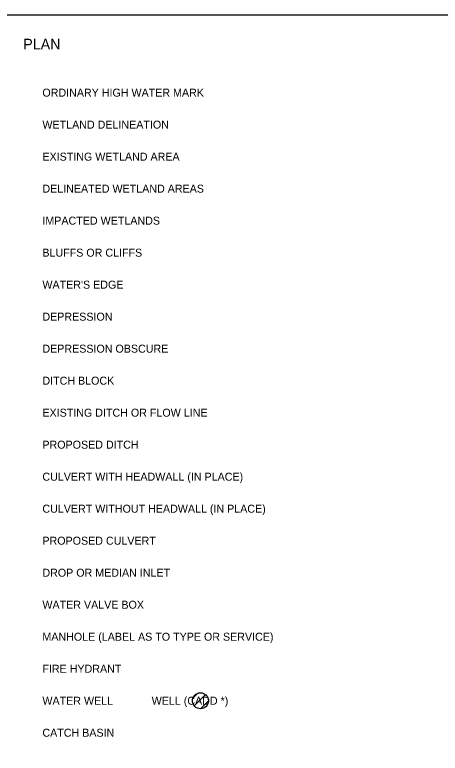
# Model space of a CAD drawing. Extents: x 49991.4 to 50021, y 49987.6 to 50011.4.
# Drawn here: x 50009.45 to 50012.64, y 49993.46 to 49999 of the extents above; entities that cross this region are included whole.
import ezdxf

# ---------------------------------------------------------------- set-up
doc = ezdxf.new("R2010")
doc.units = 0
doc.layers.add('Level 1', color=7, linetype='Continuous')
doc.layers.add('Level 2', color=7, linetype='Continuous')

msp = doc.modelspace()

# ---------------------------------------------------------------- linework, layer by layer
at = {"layer": 'Level 1'}
for p, q in [((50010.7828, 49993.874), (50010.8211, 49993.9122)), ((50010.7936, 49993.8169), (50010.8782, 49993.9014)), ((50010.8398, 49993.7952), (50010.8998, 49993.8552))]:
    msp.add_line(p, q, dxfattribs=at)
msp.add_lwpolyline([(49999.3835, 49998.9992), (50016.7501, 49998.9992), (50016.7501, 49987.7988), (49999.3835, 49987.7988)], close=True, dxfattribs=at)
msp.add_circle((50010.8398, 49993.8552), 0.06, dxfattribs=at)

# ---------------------------------------------------------------- texts
at = {"layer": 'Level 2'}
for s, height, p in [('PLAN', 0.08, (50009.5097, 49998.7392)), ('ORDINARY HIGH WATER MARK', 0.06, (50009.6535, 49998.3852)), ('WETLAND DELINEATION ', 0.06, (50009.6535, 49998.1452)), ('EXISTING WETLAND AREA', 0.06, (50009.6535, 49997.9052)), ('DELINEATED WETLAND AREAS ', 0.06, (50009.6535, 49997.6652)), ('IMPACTED WETLANDS ', 0.06, (50009.6535, 49997.4252)), ('BLUFFS OR CLIFFS    ', 0.059999, (50009.6535, 49997.1852)), ("WATER'S EDGE        ", 0.059999, (50009.6535, 49996.9452)), ('DEPRESSION          ', 0.059999, (50009.6535, 49996.7052)), ('DEPRESSION OBSCURE  ', 0.059999, (50009.6535, 49996.4652)), ('DITCH BLOCK                             ', 0.059999, (50009.6535, 49996.2252)), ('EXISTING DITCH OR FLOW LINE            ', 0.06, (50009.6535, 49995.9852)), ('PROPOSED DITCH                         ', 0.06, (50009.6535, 49995.7452)), ('CULVERT WITH HEADWALL (IN PLACE)        ', 0.059999, (50009.6535, 49995.5052)), ('CULVERT WITHOUT HEADWALL (IN PLACE)     ', 0.059999, (50009.6535, 49995.2652)), ('PROPOSED CULVERT                        ', 0.059999, (50009.6535, 49995.0252)), ('DROP OR MEDIAN INLET           ', 0.059999, (50009.6535, 49994.7852)), ('WATER VALVE BOX                         ', 0.059999, (50009.6535, 49994.5452)), ('MANHOLE (LABEL AS TO TYPE OR SERVICE)   ', 0.059999, (50009.6535, 49994.3052)), ('FIRE HYDRANT                            ', 0.059999, (50009.6535, 49994.0652)), ('WATER WELL             WELL (CADD *)     ', 0.06, (50009.6535, 49993.8252)), ('CATCH BASIN', 0.059999, (50009.6535, 49993.5852))]:
    msp.add_text(s, height=height, dxfattribs=at).set_placement(p)

doc.saveas('drawing.dxf')
